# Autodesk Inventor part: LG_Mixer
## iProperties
Shininess: 64.0
Length Units: 11269
Angle Units: 11279
Time Units: 11290
Mass Units: 11283
Length Display Precision: 3
Angle Display Precision: 2
Compacted: True
Part Number: LG_Mixer
Document SubType Name: Modeling
Created: 2004-08
Material: Lexan, Clear
Designer: John Blackburn
Manufacturer: Standard
Standards Organization: Custom
Density: 0.0
Volumn: 0.0
Area: 0.0
PropertySet Name: Model Information
Control State: 0
Master: False
Checked Out: False
Author: John Blackburn
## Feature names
1. Extrusion1
